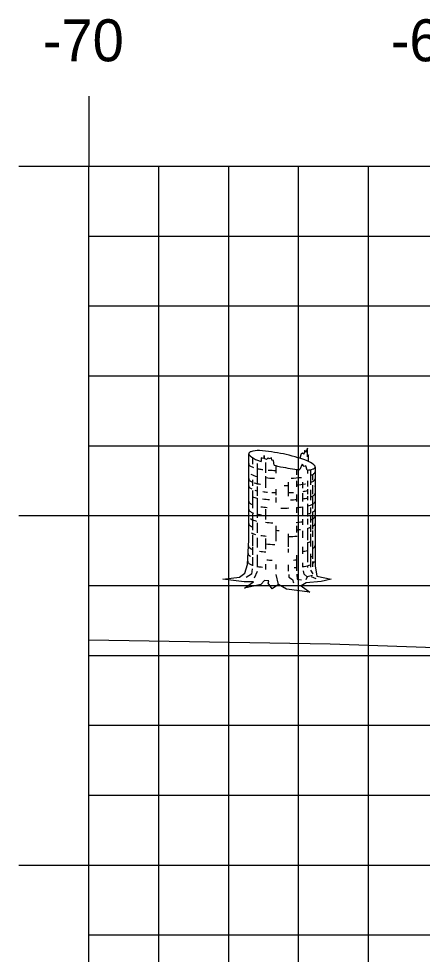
# Model space of a CAD drawing. Extents: x 1146746 to 1146916, y 608981 to 609091.
# Drawn here: x 1146758.43 to 1146764.2, y 609029.06 to 609042.44 of the extents above; entities that cross this region are included whole.
import ezdxf

# ---------------------------------------------------------------- set-up
doc = ezdxf.new("R2010")
doc.units = 0
for name, color, linetype in [('H_V ANNOTATION', 7, 'Continuous'), ('MAJOR', 7, 'Continuous'), ('MINOR', 7, 'Continuous'), ('S_Roadway_Centerline', 7, 'Continuous'), ('S_Trees_Decid_NonPay', 7, 'Continuous')]:
    doc.layers.add(name, color=color, linetype=linetype)

msp = doc.modelspace()

# ---------------------------------------------------------------- linework, layer by layer
at = {"layer": 'MAJOR'}
for p, q in [((1146759.428, 609041.337), (1146759.428, 609040.335)), ((1146758.426, 609040.335), (1146759.428, 609040.335)), ((1146759.428, 609040.335), (1146899.428, 609040.335)), ((1146759.428, 609020.335), (1146759.428, 609040.335)), ((1146759.428, 609020.335), (1146759.428, 609040.335)), ((1146759.428, 609040.335), (1146899.428, 609040.335)), ((1146758.426, 609035.335), (1146759.428, 609035.335)), ((1146759.428, 609035.335), (1146899.428, 609035.335)), ((1146758.426, 609030.335), (1146759.428, 609030.335)), ((1146759.428, 609030.335), (1146899.428, 609030.335))]:
    msp.add_line(p, q, dxfattribs=at)
at = {"layer": 'MINOR'}
for p, q in [((1146760.428, 609020.335), (1146760.428, 609040.335)), ((1146761.428, 609020.335), (1146761.428, 609040.335)), ((1146762.428, 609020.335), (1146762.428, 609040.335)), ((1146763.428, 609020.335), (1146763.428, 609040.335)), ((1146759.428, 609039.335), (1146899.428, 609039.335)), ((1146759.428, 609039.335), (1146760.43, 609039.335)), ((1146759.428, 609038.335), (1146899.428, 609038.335)), ((1146759.428, 609038.335), (1146760.43, 609038.335)), ((1146759.428, 609037.335), (1146899.428, 609037.335)), ((1146759.428, 609037.335), (1146760.43, 609037.335)), ((1146759.428, 609036.335), (1146899.428, 609036.335)), ((1146759.428, 609036.335), (1146760.43, 609036.335)), ((1146759.428, 609034.335), (1146899.428, 609034.335)), ((1146759.428, 609034.335), (1146760.43, 609034.335)), ((1146759.428, 609033.335), (1146899.428, 609033.335)), ((1146759.428, 609033.335), (1146760.43, 609033.335)), ((1146759.428, 609032.335), (1146899.428, 609032.335)), ((1146759.428, 609032.335), (1146760.43, 609032.335)), ((1146759.428, 609031.335), (1146899.428, 609031.335)), ((1146759.428, 609031.335), (1146760.43, 609031.335)), ((1146759.428, 609029.335), (1146899.428, 609029.335)), ((1146759.428, 609029.335), (1146760.43, 609029.335))]:
    msp.add_line(p, q, dxfattribs=at)
at = {"layer": 'S_Roadway_Centerline'}
msp.add_lwpolyline([(1146759.428, 609033.556), (1146762.881, 609033.501), (1146764.381, 609033.447), (1146765.249, 609033.421), (1146766.824, 609033.384), (1146767.963, 609033.367), (1146768.745, 609033.359), (1146770.475, 609033.354), (1146778.994, 609033.253), (1146779.894, 609033.259), (1146781.955, 609033.29), (1146784.763, 609033.357), (1146788.214, 609033.405), (1146790.04, 609033.481), (1146792.515, 609033.614), (1146794.858, 609033.519)], dxfattribs=at)
at = {"layer": 'S_Trees_Decid_NonPay'}
for p, q in [((1146761.767, 609036.166), (1146761.767, 609036.071)), ((1146761.835, 609036.079), (1146761.835, 609035.779)), ((1146761.954, 609036.096), (1146761.954, 609035.948)), ((1146762.101, 609036.05), (1146762.101, 609035.943)), ((1146762.398, 609035.998), (1146762.398, 609035.919)), ((1146762.555, 609035.987), (1146762.555, 609035.935)), ((1146762.598, 609035.992), (1146762.598, 609035.775)), ((1146761.767, 609035.845), (1146761.767, 609035.762)), ((1146761.954, 609035.9), (1146761.954, 609035.731)), ((1146762.625, 609035.922), (1146762.625, 609035.84)), ((1146761.835, 609035.75), (1146761.835, 609035.618)), ((1146762.101, 609035.715), (1146762.101, 609035.628)), ((1146762.28, 609035.814), (1146762.28, 609035.614)), ((1146762.398, 609035.832), (1146762.398, 609035.748)), ((1146762.484, 609035.814), (1146762.484, 609035.727)), ((1146762.555, 609035.832), (1146762.555, 609035.75)), ((1146762.555, 609035.715), (1146762.555, 609035.641)), ((1146762.625, 609035.771), (1146762.625, 609035.641)), ((1146761.767, 609035.693), (1146761.767, 609035.441)), ((1146761.835, 609035.584), (1146761.835, 609035.304)), ((1146762.101, 609035.594), (1146762.101, 609035.523)), ((1146762.398, 609035.637), (1146762.398, 609035.536)), ((1146762.484, 609035.657), (1146762.484, 609035.536)), ((1146762.555, 609035.614), (1146762.555, 609035.554)), ((1146762.598, 609035.706), (1146762.598, 609035.554)), ((1146762.625, 609035.618), (1146762.625, 609035.437)), ((1146762.398, 609035.451), (1146762.398, 609035.375)), ((1146762.484, 609035.46), (1146762.484, 609035.346)), ((1146762.555, 609035.501), (1146762.555, 609035.32)), ((1146762.598, 609035.449), (1146762.598, 609035.371)), ((1146761.767, 609035.359), (1146761.767, 609035.128)), ((1146761.954, 609035.425), (1146761.954, 609035.277)), ((1146762.598, 609035.344), (1146762.598, 609035.237)), ((1146762.625, 609035.389), (1146762.625, 609035.143)), ((1146761.835, 609035.233), (1146761.835, 609035.089)), ((1146762.101, 609035.19), (1146762.101, 609034.968)), ((1146762.398, 609035.19), (1146762.398, 609035.093)), ((1146762.484, 609035.284), (1146762.484, 609035.202)), ((1146762.555, 609035.288), (1146762.555, 609035.206)), ((1146762.598, 609035.202), (1146762.598, 609035.101)), ((1146761.767, 609035.058), (1146761.767, 609034.897)), ((1146762.28, 609035.076), (1146762.28, 609034.889)), ((1146762.484, 609035.116), (1146762.484, 609035.019)), ((1146762.555, 609035.153), (1146762.555, 609034.982)), ((1146762.598, 609035.076), (1146762.598, 609034.893)), ((1146762.625, 609035.124), (1146762.625, 609035.029)), ((1146761.835, 609035.019), (1146761.835, 609034.877)), ((1146761.954, 609035.007), (1146761.954, 609034.854)), ((1146762.555, 609034.949), (1146762.555, 609034.669)), ((1146762.627, 609034.976), (1146762.626, 609034.716)), ((1146761.767, 609034.881), (1146761.767, 609034.776)), ((1146761.835, 609034.776), (1146761.835, 609034.595)), ((1146762.28, 609034.859), (1146762.28, 609034.805)), ((1146762.484, 609034.889), (1146762.484, 609034.79)), ((1146762.598, 609034.79), (1146762.598, 609034.599)), ((1146761.767, 609034.739), (1146761.767, 609034.615)), ((1146761.954, 609034.642), (1146761.954, 609034.564)), ((1146762.398, 609034.768), (1146762.398, 609034.544)), ((1146762.484, 609034.661), (1146762.484, 609034.603)), ((1146762.625, 609034.678), (1146762.625, 609034.603)), ((1146761.834, 609034.535), (1146761.793, 609034.439)), ((1146762.101, 609034.634), (1146762.101, 609034.568)), ((1146762.28, 609034.63), (1146762.28, 609034.539)), ((1146762.555, 609034.616), (1146762.555, 609034.591)), ((1146762.596, 609034.552), (1146762.631, 609034.5)), ((1146762.141, 609034.348), (1146762.106, 609034.494)), ((1146762.678, 609034.43), (1146762.61, 609034.461))]:
    msp.add_line(p, q, dxfattribs=at)
for points in [[(1146762.571, 609036.111), (1146762.567, 609036.205), (1146762.553, 609036.178), (1146762.553, 609036.3), (1146762.532, 609036.236), (1146762.517, 609036.269), (1146762.501, 609036.213), (1146762.484, 609036.23), (1146762.466, 609036.221), (1146762.447, 609036.155)], [(1146762.666, 609036.03), (1146762.666, 609034.618), (1146762.689, 609034.47), (1146762.892, 609034.426), (1146762.752, 609034.391), (1146762.534, 609034.372), (1146762.464, 609034.329), (1146762.586, 609034.241), (1146762.254, 609034.284), (1146762.141, 609034.348), (1146762.048, 609034.288), (1146761.992, 609034.367), (1146762.001, 609034.403), (1146761.939, 609034.405), (1146761.887, 609034.348), (1146761.655, 609034.296), (1146761.782, 609034.385), (1146761.651, 609034.387), (1146761.342, 609034.424), (1146761.581, 609034.455), (1146761.659, 609034.513), (1146761.698, 609034.634), (1146761.715, 609034.988), (1146761.715, 609036.221)], [(1146762.079, 609036.055), (1146762.07, 609036.122), (1146762.046, 609036.127), (1146762.038, 609036.162), (1146762.007, 609036.147), (1146761.992, 609036.162), (1146761.968, 609036.139), (1146761.945, 609036.147), (1146761.933, 609036.197), (1146761.925, 609036.153), (1146761.894, 609036.162), (1146761.891, 609036.111)], [(1146762.549, 609035.987), (1146762.532, 609036.048), (1146762.509, 609036.036), (1146762.479, 609036.071), (1146762.445, 609035.993)], [(1146761.764, 609034.573), (1146761.755, 609034.496), (1146761.677, 609034.447)], [(1146762.548, 609034.461), (1146762.505, 609034.496), (1146762.497, 609034.544)], [(1146762.289, 609034.49), (1146762.289, 609034.453), (1146762.34, 609034.422), (1146762.357, 609034.372)], [(1146762.401, 609034.496), (1146762.406, 609034.426), (1146762.47, 609034.414)], [(1146762.627, 609034.477), (1146762.548, 609034.461), (1146762.532, 609034.418)]]:
    msp.add_lwpolyline(points, dxfattribs=at)
for centre, radius, start, end in [((1146761.775, 609036.16), 0.0935, 108.1723, 119.396), ((1146761.846, 609035.943), 0.322, 86.0543, 108.1723), ((1146761.696, 609033.763), 2.507, 78.1723, 86.0543), ((1146761.733, 609036.222), 0.0179, 152.1168, 168.1723), ((1146761.733, 609036.222), 0.0179, 168.1723, 184.2278), ((1146761.739, 609036.222), 0.0237, 184.2278, 198.1723), ((1146761.748, 609036.225), 0.0336, 198.1723, 216.9486), ((1146761.738, 609036.219), 0.0237, 138.1723, 152.1168), ((1146761.745, 609036.212), 0.0336, 119.396, 138.1723), ((1146761.796, 609036.261), 0.0935, 216.9486, 228.1723), ((1146761.948, 609036.431), 0.322, 228.1723, 250.2902), ((1146762.685, 609038.488), 2.507, 250.2902, 251.5281), ((1146761.696, 609033.763), 2.507, 70.2902, 78.1723), ((1146762.433, 609035.82), 0.322, 48.1723, 70.2902), ((1146761.733, 609036.074), 0.0191, 163.9485, 180), ((1146761.733, 609036.074), 0.0191, 180, 196.0515), ((1146761.739, 609036.076), 0.0252, 196.0515, 210), ((1146761.748, 609036.081), 0.0356, 210, 228.7494), ((1146761.79, 609036.128), 0.0984, 228.7494, 240), ((1146761.904, 609036.325), 0.326, 240, 248.3243), ((1146761.904, 609036.325), 0.326, 257.8036, 261.8968), ((1146762.19, 609038.335), 2.356, 261.8968, 263.2799), ((1146762.19, 609038.335), 2.356, 265.24, 267.8386), ((1146762.685, 609038.488), 2.507, 255.9987, 258.1723), ((1146762.685, 609038.488), 2.507, 258.1723, 264.5013), ((1146762.535, 609036.308), 0.322, 272.4479, 288.1723), ((1146762.606, 609036.091), 0.0935, 288.1723, 299.396), ((1146762.585, 609035.99), 0.0935, 36.9486, 48.1723), ((1146762.636, 609036.039), 0.0336, 299.396, 318.1723), ((1146762.633, 609036.026), 0.0336, 18.1723, 36.9486), ((1146762.643, 609036.033), 0.0237, 318.1723, 332.1168), ((1146762.648, 609036.03), 0.0179, 332.1168, 348.1723), ((1146762.642, 609036.03), 0.0237, 4.2278, 18.1723), ((1146762.648, 609036.03), 0.0179, 348.1723, 4.2278), ((1146761.733, 609035.86), 0.0191, 163.9485, 180), ((1146761.733, 609035.86), 0.0191, 180, 196.0515), ((1146761.739, 609035.862), 0.0252, 196.0515, 210), ((1146761.748, 609035.867), 0.0356, 210, 228.7494), ((1146761.904, 609036.212), 0.326, 240.9099, 257.8036), ((1146762.19, 609038.222), 2.356, 264.242, 267.3673), ((1146762.19, 609038.222), 2.356, 273.1481, 276.7734), ((1146762.476, 609036.212), 0.326, 291.9506, 300), ((1146762.59, 609036.015), 0.0984, 300, 311.2506), ((1146762.631, 609035.968), 0.0356, 311.2506, 330), ((1146762.631, 609035.867), 0.0356, 311.2506, 330), ((1146762.64, 609035.963), 0.0252, 330, 343.9485), ((1146762.64, 609035.862), 0.0252, 330, 343.9485), ((1146762.646, 609035.961), 0.0191, 343.9485, 360), ((1146762.646, 609035.86), 0.0191, 343.9485, 360), ((1146762.646, 609035.961), 0.0191, 360, 6.1128), ((1146762.646, 609035.86), 0.0191, 360, 6.1128), ((1146761.733, 609035.757), 0.0191, 163.9485, 180), ((1146761.733, 609035.757), 0.0191, 180, 196.0515), ((1146761.739, 609035.759), 0.0252, 196.0515, 210), ((1146761.748, 609035.764), 0.0356, 210, 228.7494), ((1146761.79, 609035.914), 0.0984, 228.7494, 240), ((1146761.79, 609035.811), 0.0984, 228.7494, 240), ((1146761.904, 609036.111), 0.326, 240, 243.5719), ((1146761.904, 609036.008), 0.326, 240, 243.243), ((1146761.904, 609036.111), 0.326, 250.4167, 261.8968), ((1146762.19, 609038.121), 2.356, 261.8968, 262.5519), ((1146762.19, 609038.121), 2.356, 270.8119, 272.1981), ((1146762.19, 609038.121), 2.356, 275.0647, 278.1032), ((1146762.476, 609036.111), 0.326, 278.1032, 279.0854), ((1146762.476, 609036.111), 0.326, 291.9506, 300), ((1146762.59, 609035.914), 0.0984, 300, 311.2506), ((1146762.646, 609035.757), 0.0191, 343.9485, 360), ((1146762.646, 609035.757), 0.0191, 360, 6.1128), ((1146761.904, 609035.903), 0.326, 245.1545, 257.8036), ((1146761.904, 609036.008), 0.326, 251.6831, 257.8036), ((1146762.19, 609038.018), 2.356, 263.3413, 264.9946), ((1146762.19, 609038.018), 2.356, 266.5036, 267.8386), ((1146762.19, 609038.018), 2.356, 272.1981, 273.9741), ((1146762.19, 609037.913), 2.356, 277.1868, 278.1032), ((1146762.19, 609038.018), 2.356, 277.3838, 278.1032), ((1146762.476, 609036.008), 0.326, 278.1032, 284.0382), ((1146762.476, 609035.903), 0.326, 278.1032, 284.0382), ((1146762.476, 609035.903), 0.326, 291.9506, 300), ((1146762.59, 609035.706), 0.0984, 300, 311.2506), ((1146762.631, 609035.659), 0.0356, 311.2506, 330), ((1146762.64, 609035.654), 0.0252, 330, 343.9485), ((1146762.646, 609035.652), 0.0191, 343.9485, 360), ((1146762.646, 609035.652), 0.0191, 360, 6.1128), ((1146761.733, 609035.537), 0.0191, 163.9485, 180), ((1146761.733, 609035.537), 0.0191, 180, 196.0515), ((1146761.739, 609035.539), 0.0252, 196.0515, 210), ((1146761.748, 609035.544), 0.0356, 210, 228.7494), ((1146761.79, 609035.591), 0.0984, 228.7494, 240), ((1146761.904, 609035.788), 0.326, 240, 245.1545), ((1146762.19, 609037.798), 2.356, 262.6588, 264.7911), ((1146762.19, 609037.913), 2.356, 263.2682, 265.6362), ((1146762.19, 609037.798), 2.356, 270, 272.414), ((1146762.19, 609037.913), 2.356, 273.0067, 275.0647), ((1146762.19, 609037.798), 2.356, 275.0647, 277.1868), ((1146762.476, 609035.788), 0.326, 284.0382, 300), ((1146762.59, 609035.591), 0.0984, 300, 311.2506), ((1146762.631, 609035.544), 0.0356, 311.2506, 330), ((1146762.64, 609035.539), 0.0252, 330, 343.9485), ((1146762.646, 609035.537), 0.0191, 343.9485, 360), ((1146762.646, 609035.537), 0.0191, 360, 6.1128), ((1146761.731, 609035.322), 0.0191, 163.9485, 180), ((1146761.734, 609035.423), 0.0191, 163.9485, 180), ((1146761.734, 609035.423), 0.0191, 180, 196.0515), ((1146761.74, 609035.424), 0.0252, 196.0515, 210), ((1146761.749, 609035.43), 0.0356, 210, 228.7494), ((1146761.79, 609035.477), 0.0984, 228.7494, 240), ((1146761.904, 609035.674), 0.326, 240, 247.8656), ((1146761.904, 609035.674), 0.326, 257.6699, 261.8968), ((1146762.191, 609037.684), 2.356, 261.8968, 262.8615), ((1146762.19, 609037.798), 2.356, 269.5578, 270), ((1146762.477, 609035.674), 0.326, 283.9036, 291.8098), ((1146762.477, 609035.674), 0.326, 297.0058, 300), ((1146762.591, 609035.477), 0.0984, 300, 311.2506), ((1146762.629, 609035.329), 0.0356, 311.2506, 330), ((1146762.632, 609035.43), 0.0356, 311.2506, 330), ((1146762.638, 609035.324), 0.0252, 330, 343.9485), ((1146762.644, 609035.322), 0.0191, 343.9485, 360), ((1146762.641, 609035.424), 0.0252, 330, 343.9485), ((1146762.644, 609035.322), 0.0191, 0, 6.1128), ((1146762.647, 609035.423), 0.0191, 343.9485, 360), ((1146762.647, 609035.423), 0.0191, 0, 6.1128), ((1146761.733, 609035.218), 0.0191, 163.9485, 180), ((1146761.733, 609035.218), 0.0191, 180, 196.0515), ((1146761.739, 609035.219), 0.0252, 196.0515, 210), ((1146761.748, 609035.225), 0.0356, 210, 228.7494), ((1146761.79, 609035.272), 0.0984, 228.7494, 240), ((1146761.901, 609035.574), 0.326, 240, 256.9079), ((1146761.904, 609035.469), 0.326, 240, 245.1545), ((1146762.187, 609037.584), 2.356, 264.3443, 266.8529), ((1146762.187, 609037.584), 2.356, 274.9734, 277.2455), ((1146762.474, 609035.574), 0.326, 292.4049, 300), ((1146762.476, 609035.469), 0.326, 297.1525, 300), ((1146762.587, 609035.376), 0.0984, 300, 311.2506), ((1146762.59, 609035.272), 0.0984, 300, 311.2506), ((1146762.631, 609035.225), 0.0356, 311.2506, 330), ((1146762.64, 609035.219), 0.0252, 330, 343.9485), ((1146762.646, 609035.218), 0.0191, 343.9485, 360), ((1146762.646, 609035.218), 0.0191, 360, 6.1128), ((1146761.904, 609035.378), 0.326, 241.939, 253.9183), ((1146762.19, 609037.388), 2.356, 262.5843, 264.4865), ((1146762.19, 609037.479), 2.356, 267.8386, 269.0054), ((1146762.19, 609037.388), 2.356, 272.1981, 275.2726), ((1146762.19, 609037.479), 2.356, 275.0647, 276.428), ((1146762.476, 609035.469), 0.326, 284.0382, 291.9506), ((1146762.646, 609035.127), 0.0191, 360, 6.1128), ((1146762.19, 609037.275), 2.356, 264.242, 267.469), ((1146762.476, 609035.265), 0.326, 284.0382, 291.9506), ((1146761.724, 609034.788), 0.0191, 163.9485, 180), ((1146761.724, 609034.788), 0.0191, 180, 196.0515), ((1146761.73, 609034.79), 0.0252, 196.0515, 210), ((1146761.739, 609034.795), 0.0356, 210, 228.7494), ((1146761.729, 609034.899), 0.0191, 163.9485, 180), ((1146761.729, 609034.899), 0.0191, 180, 196.0515), ((1146761.735, 609034.9), 0.0252, 196.0515, 210), ((1146761.744, 609034.905), 0.0356, 210, 228.7494), ((1146761.786, 609034.953), 0.0984, 228.7494, 240), ((1146761.9, 609035.15), 0.326, 240, 245.9375), ((1146762.186, 609037.16), 2.356, 262.2226, 264.4852), ((1146762.186, 609037.16), 2.356, 277.2863, 278.1032), ((1146762.472, 609035.15), 0.326, 278.1032, 284.7741), ((1146762.586, 609034.953), 0.0984, 300, 311.2506), ((1146762.627, 609034.905), 0.0356, 311.2506, 330), ((1146762.636, 609034.9), 0.0252, 330, 343.9485), ((1146762.642, 609034.899), 0.0191, 343.9485, 360), ((1146762.642, 609034.899), 0.0191, 360, 6.1128), ((1146761.719, 609034.678), 0.0191, 163.9485, 180), ((1146761.719, 609034.678), 0.0191, 180, 196.0515), ((1146761.725, 609034.679), 0.0252, 196.0515, 210), ((1146761.734, 609034.685), 0.0356, 210, 228.7494), ((1146761.775, 609034.732), 0.0984, 228.7494, 240), ((1146761.781, 609034.842), 0.0984, 228.7494, 240), ((1146761.889, 609034.929), 0.326, 240, 247.9161), ((1146761.895, 609035.039), 0.326, 240, 241.9097), ((1146762.181, 609037.049), 2.356, 264.9089, 266.8158), ((1146762.181, 609037.049), 2.356, 274.1864, 275.2829), ((1146762.467, 609035.039), 0.326, 293.6544, 300), ((1146762.575, 609034.732), 0.0984, 300, 311.2506), ((1146762.617, 609034.685), 0.0356, 311.2506, 330), ((1146762.626, 609034.679), 0.0252, 330, 343.9485), ((1146762.632, 609034.678), 0.0191, 343.9485, 360), ((1146762.632, 609034.678), 0.0191, 0, 6.1128), ((1146761.889, 609034.929), 0.326, 260.3834, 261.8968), ((1146762.175, 609036.939), 2.356, 261.8968, 263.5333), ((1146762.175, 609036.939), 2.356, 274.5551, 275.4167), ((1146762.175, 609036.939), 2.356, 277.5403, 278.1032), ((1146762.462, 609034.929), 0.326, 278.1032, 294.7094)]:
    msp.add_arc(centre, radius, start, end, dxfattribs=at)

# ---------------------------------------------------------------- texts
at = {"layer": 'H_V ANNOTATION'}
for s, p in [('-70', (1146758.769, 609041.835)), ('-65', (1146763.745, 609041.835))]:
    msp.add_text(s, height=0.6, dxfattribs=at).set_placement(p)

doc.saveas('drawing.dxf')
